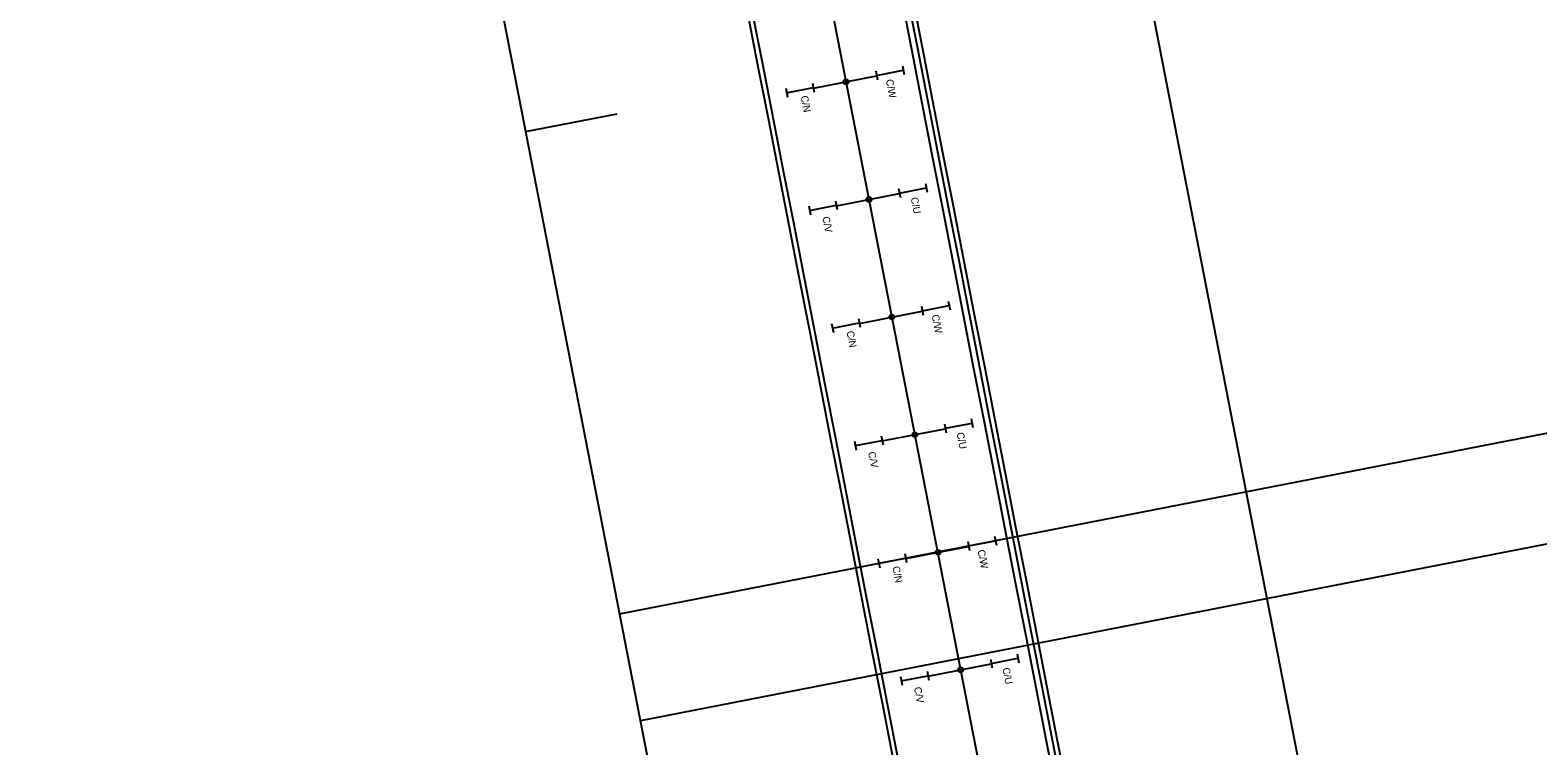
# Model space of a CAD drawing. Extents: x -545258 to -544992, y -1122311 to -1121664.
# Drawn here: x -545196.1 to -545140.8, y -1122127.2 to -1122101 of the extents above; entities that cross this region are included whole.
import ezdxf

# ---------------------------------------------------------------- set-up
doc = ezdxf.new("R2010")
doc.units = 0
for name, color, linetype in [('SO 18-01-01_3', 7, 'Continuous'), ('SO18-15-04', 7, 'Continuous'), ('SO18-15-08', 7, 'Continuous'), ('SO18-16-02', 7, 'Continuous'), ('so180605', 7, 'Continuous'), ('Vrstva 10', 7, 'Continuous')]:
    doc.layers.add(name, color=color, linetype=linetype)

msp = doc.modelspace()

# ---------------------------------------------------------------- linework, layer by layer
at = {"layer": 'SO 18-01-01_3'}
for p, q in [((-545174.491, -1122122.395), (-545121.511, -1122112.067)), ((-545120.746, -1122115.994), (-545173.725, -1122126.321))]:
    msp.add_line(p, q, dxfattribs=at)
at = {"layer": 'SO18-15-04'}
for centre in [(-545166.172, -1122102.856), (-545165.33, -1122107.175), (-545164.488, -1122111.493), (-545163.646, -1122115.812), (-545162.787, -1122120.131), (-545161.963, -1122124.449)]:
    msp.add_circle(centre, 0.09, dxfattribs=at)
at = {"layer": 'SO18-16-02'}
for points in [[(-545158.41, -1122129.096), (-545158.793, -1122127.133), (-545159.176, -1122125.17), (-545159.558, -1122123.207), (-545159.941, -1122121.244), (-545160.324, -1122119.281), (-545160.706, -1122117.318), (-545161.089, -1122115.355), (-545161.471, -1122113.392), (-545161.854, -1122111.428), (-545162.237, -1122109.465), (-545162.619, -1122107.503), (-545163.002, -1122105.539), (-545163.385, -1122103.576), (-545163.767, -1122101.613), (-545164.15, -1122099.65)], [(-545158.194, -1122129.054), (-545158.577, -1122127.091), (-545158.96, -1122125.128), (-545159.342, -1122123.165), (-545159.725, -1122121.202), (-545160.108, -1122119.239), (-545160.49, -1122117.276), (-545160.873, -1122115.313), (-545161.256, -1122113.349), (-545161.638, -1122111.386), (-545162.021, -1122109.423), (-545162.404, -1122107.46), (-545162.786, -1122105.497), (-545163.169, -1122103.534), (-545163.552, -1122101.571), (-545163.934, -1122099.608)], [(-545158.018, -1122129.02), (-545158.4, -1122127.056), (-545158.783, -1122125.093), (-545159.166, -1122123.13), (-545159.548, -1122121.167), (-545159.931, -1122119.204), (-545160.314, -1122117.241), (-545160.696, -1122115.278), (-545161.079, -1122113.315), (-545161.462, -1122111.352), (-545161.844, -1122109.389), (-545162.227, -1122107.426), (-545162.61, -1122105.463), (-545162.992, -1122103.5), (-545163.375, -1122101.537), (-545163.757, -1122099.574)], [(-545169.802, -1122100.268), (-545169.419, -1122102.231), (-545169.037, -1122104.194), (-545168.654, -1122106.157), (-545168.271, -1122108.12), (-545167.888, -1122110.083), (-545167.505, -1122112.046), (-545167.122, -1122114.009), (-545166.739, -1122115.972), (-545166.356, -1122117.935), (-545165.974, -1122119.898), (-545165.591, -1122121.861), (-545165.208, -1122123.824), (-545164.825, -1122125.787), (-545164.442, -1122127.75)], [(-545169.626, -1122100.234), (-545169.243, -1122102.197), (-545168.86, -1122104.16), (-545168.477, -1122106.123), (-545168.094, -1122108.086), (-545167.711, -1122110.049), (-545167.328, -1122112.012), (-545166.946, -1122113.975), (-545166.563, -1122115.938), (-545166.18, -1122117.901), (-545165.797, -1122119.864), (-545165.414, -1122121.827), (-545165.031, -1122123.79), (-545164.648, -1122125.753), (-545164.265, -1122127.716)]]:
    msp.add_lwpolyline(points, dxfattribs=at)
at = {"layer": 'so180605'}
for p, q in [((-545156.903, -1122090.087), (-545130.303, -1122226.573)), ((-545165.081, -1122102.457), (-545165.016, -1122102.785)), ((-545165.05, -1122102.623), (-545164.068, -1122102.431)), ((-545164.098, -1122102.268), (-545164.035, -1122102.594)), ((-545168.383, -1122103.093), (-545168.319, -1122103.422)), ((-545168.353, -1122103.26), (-545167.371, -1122103.068)), ((-545167.401, -1122102.905), (-545167.338, -1122103.231)), ((-545164.239, -1122106.775), (-545164.175, -1122107.104)), ((-545164.208, -1122106.941), (-545163.226, -1122106.75)), ((-545163.257, -1122106.587), (-545163.193, -1122106.912)), ((-545167.542, -1122107.412), (-545167.478, -1122107.741)), ((-545167.511, -1122107.578), (-545166.529, -1122107.387)), ((-545166.56, -1122107.224), (-545166.496, -1122107.549)), ((-545162.415, -1122110.905), (-545162.351, -1122111.231)), ((-545165.718, -1122111.542), (-545165.654, -1122111.868)), ((-545163.397, -1122111.094), (-545163.333, -1122111.422)), ((-545163.366, -1122111.26), (-545162.384, -1122111.069)), ((-545166.7, -1122111.731), (-545166.636, -1122112.059)), ((-545166.669, -1122111.897), (-545165.687, -1122111.706)), ((-545162.555, -1122115.413), (-545162.491, -1122115.741)), ((-545162.524, -1122115.579), (-545161.543, -1122115.387)), ((-545161.573, -1122115.224), (-545161.509, -1122115.55)), ((-545164.876, -1122115.861), (-545164.812, -1122116.187)), ((-545165.858, -1122116.05), (-545165.794, -1122116.378)), ((-545165.827, -1122116.216), (-545164.845, -1122116.024)), ((-545161.695, -1122119.732), (-545161.631, -1122120.06)), ((-545161.664, -1122119.898), (-545160.683, -1122119.706)), ((-545160.713, -1122119.543), (-545160.65, -1122119.869)), ((-545164.998, -1122120.369), (-545164.934, -1122120.697)), ((-545164.967, -1122120.535), (-545163.986, -1122120.343)), ((-545164.016, -1122120.18), (-545163.953, -1122120.506)), ((-545160.871, -1122124.05), (-545160.807, -1122124.379)), ((-545160.84, -1122124.216), (-545159.859, -1122124.025)), ((-545159.889, -1122123.862), (-545159.826, -1122124.187)), ((-545164.174, -1122124.687), (-545164.11, -1122125.016)), ((-545164.143, -1122124.853), (-545163.162, -1122124.662)), ((-545163.192, -1122124.499), (-545163.129, -1122124.824))]:
    msp.add_line(p, q, dxfattribs=at)
for points in [[(-545194.521, -1121957.392), (-545141.759, -1122228.099)], [(-545167.366, -1122103.088), (-545165.054, -1122102.638)], [(-545166.524, -1122107.407), (-545164.212, -1122106.957)], [(-545165.682, -1122111.725), (-545163.37, -1122111.275)], [(-545164.84, -1122116.044), (-545162.528, -1122115.594)], [(-545163.981, -1122120.363), (-545161.669, -1122119.913)], [(-545163.156, -1122124.682), (-545160.844, -1122124.232)]]:
    msp.add_lwpolyline(points, dxfattribs=at)
at = {"layer": 'Vrstva 10'}
for p, q in [((-545258.291, -1121692.439), (-545137.778, -1122310.805)), ((-545177.949, -1122104.683), (-545174.581, -1122104.027))]:
    msp.add_line(p, q, dxfattribs=at)

# ---------------------------------------------------------------- texts
at = {"layer": 'SO18-15-08'}
for s, p in [('C/W', (-545164.712, -1122102.788)), ('C/N', (-545167.84, -1122103.391)), ('C/U', (-545163.797, -1122107.118)), ('C/V', (-545167.046, -1122107.826)), ('C/W', (-545163.028, -1122111.426)), ('C/N', (-545166.156, -1122112.029)), ('C/U', (-545162.113, -1122115.755)), ('C/V', (-545165.363, -1122116.463)), ('C/W', (-545161.345, -1122120.063)), ('C/N', (-545164.473, -1122120.666)), ('C/U', (-545160.43, -1122124.392)), ('C/V', (-545163.679, -1122125.101))]:
    msp.add_text(s, height=0.2688, rotation=281.121, dxfattribs=at).set_placement(p)

doc.saveas('drawing.dxf')
